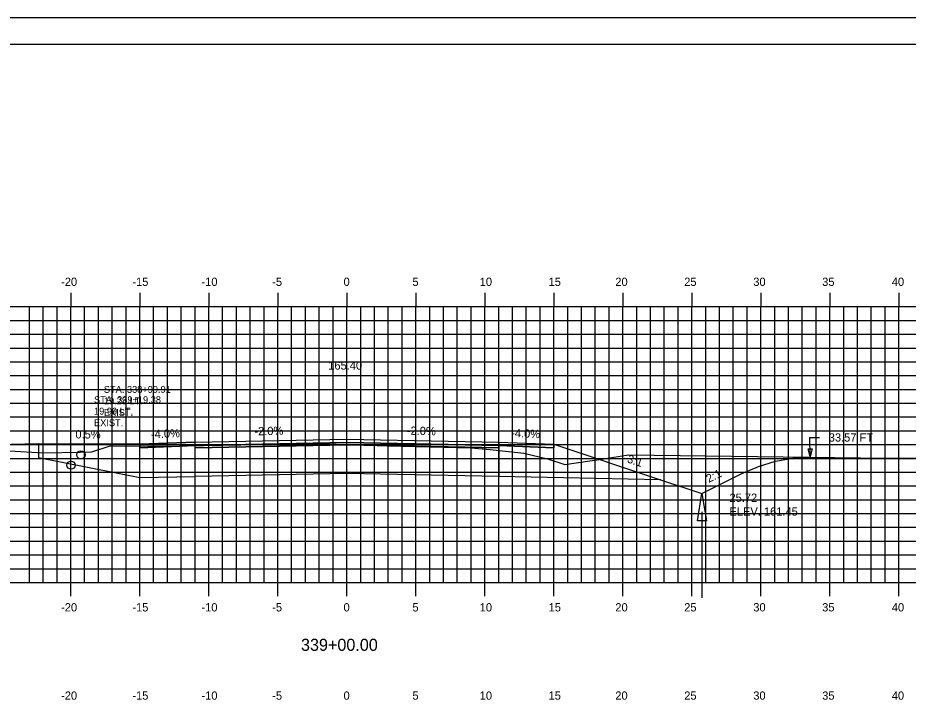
# Model space of a CAD drawing. Extents: x 1142533 to 1142703, y 608981 to 609091.
# Drawn here: x 1142592.2 to 1142656.7, y 609041.6 to 609091.3 of the extents above; entities that cross this region are included whole.
import ezdxf

# ---------------------------------------------------------------- set-up
doc = ezdxf.new("R2010")
doc.units = 0
for name, color, linetype in [('ANNOTATION', 7, 'Continuous'), ('BORDER', 7, 'Continuous'), ('D_Drainage_Ditch_Line', 7, 'Continuous'), ('D_Roadway_Centerline', 7, 'Continuous'), ('D_Roadway_Centerline_Text', 7, 'Continuous'), ('D_Roadway_Edge_Shoulder', 7, 'Continuous'), ('D_Roadway_Edge_TW', 7, 'Continuous'), ('D_Roadway_Pavement', 7, 'Continuous'), ('D_Roadway_SlopeLines', 7, 'Continuous'), ('D_Roadway_SubGrade', 7, 'Continuous'), ('D_Text_Monospaced', 7, 'Continuous'), ('D_Text_Standard', 7, 'Continuous'), ('H_V ANNOTATION', 7, 'Continuous'), ('MAJOR', 7, 'Continuous'), ('MINOR', 7, 'Continuous'), ('PLOT BOUNDARY', 7, 'Continuous'), ('S_Drainage_Invert', 7, 'Continuous'), ('S_Roadway_Centerline', 7, 'Continuous')]:
    doc.layers.add(name, color=color, linetype=linetype)

msp = doc.modelspace()

# ---------------------------------------------------------------- linework, layer by layer
msp.add_lwpolyline([(1142593.711, 609060.391), (1142601.053, 609060.355), (1142605.053, 609060.515), (1142616.053, 609060.735), (1142627.053, 609060.515), (1142631.053, 609060.355), (1142638.777, 609057.78), (1142641.777, 609056.78), (1142644.62, 609058.202), (1142645.87, 609058.747), (1142647.12, 609059.131), (1142648.37, 609059.355), (1142649.62, 609059.418)])
at = {"layer": 'BORDER'}
msp.add_lwpolyline([(1142541.054, 608984.335), (1142701.054, 608984.335), (1142701.054, 609089.335), (1142541.054, 609089.335)], close=True, dxfattribs=at)
at = {"layer": 'D_Drainage_Ditch_Line'}
msp.add_line((1142641.777, 609055.468), (1142641.777, 609049.224), dxfattribs=at)
msp.add_lwpolyline([(1142642.105, 609054.812), (1142641.449, 609054.812), (1142641.777, 609056.78)], close=True, dxfattribs=at)
at = {"layer": 'D_Roadway_Edge_Shoulder'}
for points in [[(1142605.053, 609060.515), (1142601.053, 609060.355), (1142601.053, 609060.105), (1142605.053, 609060.265)], [(1142627.053, 609060.515), (1142631.053, 609060.355), (1142631.053, 609060.105), (1142627.053, 609060.265)]]:
    msp.add_lwpolyline(points, close=True, dxfattribs=at)
at = {"layer": 'D_Roadway_Edge_TW'}
msp.add_lwpolyline([(1142605.053, 609060.265), (1142605.053, 609060.515), (1142616.053, 609060.735), (1142627.053, 609060.515), (1142627.053, 609060.265), (1142616.053, 609060.485)], close=True, dxfattribs=at)
at = {"layer": 'D_Roadway_Pavement'}
msp.add_lwpolyline([(1142605.053, 609060.098), (1142605.053, 609060.265), (1142616.053, 609060.485), (1142627.053, 609060.265), (1142627.053, 609060.098), (1142616.053, 609060.318)], close=True, dxfattribs=at)
at = {"layer": 'D_Roadway_SlopeLines'}
msp.add_line((1142593.711, 609060.391), (1142583.639, 609060.126), dxfattribs=at)
for points in [[(1142641.777, 609056.78), (1142644.62, 609058.202), (1142645.87, 609058.747), (1142647.12, 609059.131), (1142648.37, 609059.355), (1142649.62, 609059.418)], [(1142638.777, 609057.78), (1142641.777, 609056.78)]]:
    msp.add_lwpolyline(points, dxfattribs=at)
at = {"layer": 'D_Roadway_SubGrade'}
for points in [[(1142593.711, 609059.391), (1142601.053, 609057.935), (1142605.053, 609058.015), (1142605.053, 609060.098), (1142605.053, 609060.265), (1142601.053, 609060.105), (1142601.053, 609060.355), (1142593.711, 609060.391)], [(1142605.053, 609058.015), (1142605.053, 609060.098), (1142616.053, 609060.318), (1142627.053, 609060.098), (1142627.053, 609058.015), (1142616.053, 609058.235)], [(1142627.053, 609060.098), (1142627.053, 609060.265), (1142631.053, 609060.105), (1142631.053, 609060.355), (1142631.054, 609060.355), (1142638.777, 609057.78), (1142627.053, 609058.015)]]:
    msp.add_lwpolyline(points, close=True, dxfattribs=at)
at = {"layer": 'D_Text_Standard'}
msp.add_lwpolyline([(1142649.62, 609059.452), (1142649.611, 609060.849), (1142650.291, 609060.849)], dxfattribs=at)
msp.add_lwpolyline([(1142649.62, 609059.452), (1142649.471, 609060.033), (1142649.762, 609060.035)], close=True, dxfattribs=at)
at = {"layer": 'MAJOR'}
for p, q in [((1142596.053, 609071.337), (1142596.053, 609070.335)), ((1142601.053, 609071.337), (1142601.053, 609070.335)), ((1142606.053, 609071.337), (1142606.053, 609070.335)), ((1142611.053, 609071.337), (1142611.053, 609070.335)), ((1142616.053, 609071.337), (1142616.053, 609070.335)), ((1142621.053, 609071.337), (1142621.053, 609070.335)), ((1142626.053, 609071.337), (1142626.053, 609070.335)), ((1142631.053, 609071.337), (1142631.053, 609070.335)), ((1142636.053, 609071.337), (1142636.053, 609070.335)), ((1142641.053, 609071.337), (1142641.053, 609070.335)), ((1142646.053, 609071.337), (1142646.053, 609070.335)), ((1142651.053, 609071.337), (1142651.053, 609070.335)), ((1142656.053, 609071.337), (1142656.053, 609070.335)), ((1142546.053, 609070.335), (1142686.053, 609070.335)), ((1142546.053, 609070.335), (1142686.053, 609070.335)), ((1142596.053, 609050.335), (1142596.053, 609070.335)), ((1142601.053, 609050.335), (1142601.053, 609070.335)), ((1142606.053, 609050.335), (1142606.053, 609070.335)), ((1142611.053, 609050.335), (1142611.053, 609070.335)), ((1142616.053, 609050.335), (1142616.053, 609070.335)), ((1142621.053, 609050.335), (1142621.053, 609070.335)), ((1142626.053, 609050.335), (1142626.053, 609070.335)), ((1142631.053, 609050.335), (1142631.053, 609070.335)), ((1142636.053, 609050.335), (1142636.053, 609070.335)), ((1142641.053, 609050.335), (1142641.053, 609070.335)), ((1142646.053, 609050.335), (1142646.053, 609070.335)), ((1142651.053, 609050.335), (1142651.053, 609070.335)), ((1142656.053, 609050.335), (1142656.053, 609070.335)), ((1142546.053, 609065.335), (1142686.053, 609065.335)), ((1142546.053, 609060.335), (1142686.053, 609060.335)), ((1142546.053, 609055.335), (1142686.053, 609055.335)), ((1142546.053, 609050.335), (1142686.053, 609050.335)), ((1142546.053, 609050.335), (1142686.053, 609050.335)), ((1142596.053, 609049.333), (1142596.053, 609050.335)), ((1142601.053, 609049.333), (1142601.053, 609050.335)), ((1142606.053, 609049.333), (1142606.053, 609050.335)), ((1142611.053, 609049.333), (1142611.053, 609050.335)), ((1142616.053, 609049.333), (1142616.053, 609050.335)), ((1142621.053, 609049.333), (1142621.053, 609050.335)), ((1142626.053, 609049.333), (1142626.053, 609050.335)), ((1142631.053, 609049.333), (1142631.053, 609050.335)), ((1142636.053, 609049.333), (1142636.053, 609050.335)), ((1142641.053, 609049.333), (1142641.053, 609050.335)), ((1142646.053, 609049.333), (1142646.053, 609050.335)), ((1142651.053, 609049.333), (1142651.053, 609050.335)), ((1142656.053, 609049.333), (1142656.053, 609050.335))]:
    msp.add_line(p, q, dxfattribs=at)
at = {"layer": 'MINOR'}
for p, q in [((1142593.053, 609050.335), (1142593.053, 609070.335)), ((1142594.053, 609050.335), (1142594.053, 609070.335)), ((1142595.053, 609050.335), (1142595.053, 609070.335)), ((1142597.053, 609050.335), (1142597.053, 609070.335)), ((1142598.053, 609050.335), (1142598.053, 609070.335)), ((1142599.053, 609050.335), (1142599.053, 609070.335)), ((1142600.053, 609050.335), (1142600.053, 609070.335)), ((1142602.053, 609050.335), (1142602.053, 609070.335)), ((1142603.053, 609050.335), (1142603.053, 609070.335)), ((1142604.053, 609050.335), (1142604.053, 609070.335)), ((1142605.053, 609050.335), (1142605.053, 609070.335)), ((1142607.053, 609050.335), (1142607.053, 609070.335)), ((1142608.053, 609050.335), (1142608.053, 609070.335)), ((1142609.053, 609050.335), (1142609.053, 609070.335)), ((1142610.053, 609050.335), (1142610.053, 609070.335)), ((1142612.053, 609050.335), (1142612.053, 609070.335)), ((1142613.053, 609050.335), (1142613.053, 609070.335)), ((1142614.053, 609050.335), (1142614.053, 609070.335)), ((1142615.053, 609050.335), (1142615.053, 609070.335)), ((1142617.053, 609050.335), (1142617.053, 609070.335)), ((1142618.053, 609050.335), (1142618.053, 609070.335)), ((1142619.053, 609050.335), (1142619.053, 609070.335)), ((1142620.053, 609050.335), (1142620.053, 609070.335)), ((1142622.053, 609050.335), (1142622.053, 609070.335)), ((1142623.053, 609050.335), (1142623.053, 609070.335)), ((1142624.053, 609050.335), (1142624.053, 609070.335)), ((1142625.053, 609050.335), (1142625.053, 609070.335)), ((1142627.053, 609050.335), (1142627.053, 609070.335)), ((1142628.053, 609050.335), (1142628.053, 609070.335)), ((1142629.053, 609050.335), (1142629.053, 609070.335)), ((1142630.053, 609050.335), (1142630.053, 609070.335)), ((1142632.053, 609050.335), (1142632.053, 609070.335)), ((1142633.053, 609050.335), (1142633.053, 609070.335)), ((1142634.053, 609050.335), (1142634.053, 609070.335)), ((1142635.053, 609050.335), (1142635.053, 609070.335)), ((1142637.053, 609050.335), (1142637.053, 609070.335)), ((1142638.053, 609050.335), (1142638.053, 609070.335)), ((1142639.053, 609050.335), (1142639.053, 609070.335)), ((1142640.053, 609050.335), (1142640.053, 609070.335)), ((1142642.053, 609050.335), (1142642.053, 609070.335)), ((1142643.053, 609050.335), (1142643.053, 609070.335)), ((1142644.053, 609050.335), (1142644.053, 609070.335)), ((1142645.053, 609050.335), (1142645.053, 609070.335)), ((1142647.053, 609050.335), (1142647.053, 609070.335)), ((1142648.053, 609050.335), (1142648.053, 609070.335)), ((1142649.053, 609050.335), (1142649.053, 609070.335)), ((1142650.053, 609050.335), (1142650.053, 609070.335)), ((1142652.053, 609050.335), (1142652.053, 609070.335)), ((1142653.053, 609050.335), (1142653.053, 609070.335)), ((1142654.053, 609050.335), (1142654.053, 609070.335)), ((1142655.053, 609050.335), (1142655.053, 609070.335)), ((1142546.053, 609069.335), (1142686.053, 609069.335)), ((1142546.053, 609068.335), (1142686.053, 609068.335)), ((1142546.053, 609067.335), (1142686.053, 609067.335)), ((1142546.053, 609066.335), (1142686.053, 609066.335)), ((1142546.053, 609064.335), (1142686.053, 609064.335)), ((1142546.053, 609063.335), (1142686.053, 609063.335)), ((1142546.053, 609062.335), (1142686.053, 609062.335)), ((1142546.053, 609061.335), (1142686.053, 609061.335)), ((1142546.053, 609059.335), (1142686.053, 609059.335)), ((1142546.053, 609058.335), (1142686.053, 609058.335)), ((1142546.053, 609057.335), (1142686.053, 609057.335)), ((1142546.053, 609056.335), (1142686.053, 609056.335)), ((1142546.053, 609054.335), (1142686.053, 609054.335)), ((1142546.053, 609053.335), (1142686.053, 609053.335)), ((1142546.053, 609052.335), (1142686.053, 609052.335)), ((1142546.053, 609051.335), (1142686.053, 609051.335))]:
    msp.add_line(p, q, dxfattribs=at)
at = {"layer": 'PLOT BOUNDARY'}
msp.add_lwpolyline([(1142532.96, 608981.276), (1142702.96, 608981.276), (1142702.96, 609091.276), (1142532.96, 609091.276)], close=True, dxfattribs=at)
at = {"layer": 'S_Drainage_Invert'}
for centre in [(1142596.778, 609059.586), (1142596.065, 609058.84)]:
    msp.add_circle(centre, 0.3, dxfattribs=at)
at = {"layer": 'S_Roadway_Centerline'}
msp.add_lwpolyline([(1142546.053, 609060.596), (1142564.136, 609060.407), (1142571.113, 609060.438), (1142586.023, 609060.066), (1142589.149, 609060.035), (1142594.057, 609059.733), (1142596.736, 609059.787), (1142597.575, 609059.795), (1142598.896, 609060.234), (1142602.888, 609060.217), (1142602.895, 609060.218), (1142602.929, 609060.219), (1142613.821, 609060.416), (1142618.977, 609060.242), (1142625.024, 609060.106), (1142626.441, 609059.985), (1142628.873, 609059.705), (1142630.597, 609059.311), (1142631.85, 609058.883), (1142634.658, 609059.303), (1142636.46, 609059.594), (1142653.28, 609059.37), (1142667.439, 609059.325), (1142686.053, 609059.248)], dxfattribs=at)

# ---------------------------------------------------------------- texts
at = {"layer": 'ANNOTATION'}
for s, rotation, p in [('0.5%', 359.71352, (1142596.381, 609060.778)), ('-4.0%', 2.29061, (1142601.869, 609060.788)), ('-2.0%', 1.14576, (1142609.356, 609061.001)), ('-2.0%', 358.85424, (1142620.396, 609061.048)), ('-4.0%', 357.70939, (1142627.949, 609060.88)), ('-3:1', 341.56521, (1142636.065, 609059.138)), ('2:1', 26.56505, (1142642.271, 609057.545))]:
    msp.add_text(s, height=0.6, rotation=rotation, dxfattribs=at).set_placement(p)
at = {"layer": 'D_Roadway_Centerline'}
for s, p in [('C', (1142616.048, 609060.735)), ('L', (1142616.053, 609060.727))]:
    msp.add_text(s, height=0.0146, dxfattribs=at).set_placement(p)
at = {"layer": 'D_Roadway_Centerline_Text'}
msp.add_text('165.40', height=0.6, dxfattribs=at).set_placement((1142614.705, 609065.767))
at = {"layer": 'D_Text_Monospaced'}
for s, height, p in [('STA. 338+99.91', 0.49998, (1142598.445, 609064.084)), ('STA. 339+19.38', 0.49998, (1142597.732, 609063.338)), ('19.28 LT.', 0.5, (1142598.445, 609063.25)), ('19.99 LT.', 0.5, (1142597.732, 609062.504)), ('EXIST. ', 0.5, (1142598.445, 609062.41)), ('EXIST. ', 0.5, (1142597.732, 609061.664))]:
    msp.add_text(s, height=height, dxfattribs=at).set_placement(p)
at = {"layer": 'D_Text_Standard'}
for s, p in [('33.57 FT', (1142650.971, 609060.549)), ('25.72', (1142643.777, 609056.18)), ('ELEV. 161.45', (1142643.777, 609055.178))]:
    msp.add_text(s, height=0.6, dxfattribs=at).set_placement(p)
at = {"layer": 'H_V ANNOTATION'}
for s, height, p in [('-20', 0.6, (1142595.347, 609071.835)), ('-15', 0.6, (1142600.51, 609071.835)), ('-10', 0.6, (1142605.518, 609071.835)), ('-5', 0.6, (1142610.644, 609071.835)), ('0', 0.6, (1142615.813, 609071.835)), ('5', 0.6, (1142620.804, 609071.835)), ('10', 0.6, (1142625.679, 609071.835)), ('15', 0.6, (1142630.671, 609071.835)), ('20', 0.6, (1142635.507, 609071.835)), ('25', 0.6, (1142640.499, 609071.835)), ('30', 0.6, (1142645.502, 609071.835)), ('35', 0.6, (1142650.494, 609071.835)), ('40', 0.6, (1142655.54, 609071.835)), ('-20', 0.6, (1142595.347, 609048.235)), ('-15', 0.6, (1142600.51, 609048.235)), ('-10', 0.6, (1142605.518, 609048.235)), ('-5', 0.6, (1142610.644, 609048.235)), ('0', 0.6, (1142615.813, 609048.235)), ('5', 0.6, (1142620.804, 609048.235)), ('10', 0.6, (1142625.679, 609048.235)), ('15', 0.6, (1142630.671, 609048.235)), ('20', 0.6, (1142635.507, 609048.235)), ('25', 0.6, (1142640.499, 609048.235)), ('30', 0.6, (1142645.502, 609048.235)), ('35', 0.6, (1142650.494, 609048.235)), ('40', 0.6, (1142655.54, 609048.235)), ('339+00.00', 0.875, (1142612.729, 609045.378)), ('-20', 0.6, (1142595.347, 609041.835)), ('-15', 0.6, (1142600.51, 609041.835)), ('-10', 0.6, (1142605.518, 609041.835)), ('-5', 0.6, (1142610.644, 609041.835)), ('0', 0.6, (1142615.813, 609041.835)), ('5', 0.6, (1142620.804, 609041.835)), ('10', 0.6, (1142625.679, 609041.835)), ('15', 0.6, (1142630.671, 609041.835)), ('20', 0.6, (1142635.507, 609041.835)), ('25', 0.6, (1142640.499, 609041.835)), ('30', 0.6, (1142645.502, 609041.835)), ('35', 0.6, (1142650.494, 609041.835)), ('40', 0.6, (1142655.54, 609041.835))]:
    msp.add_text(s, height=height, dxfattribs=at).set_placement(p)
at = {"layer": 'S_Roadway_Centerline'}
for s, p in [('L', (1142613.813, 609060.409)), ('C', (1142613.816, 609060.416))]:
    msp.add_text(s, height=0.0146, dxfattribs=at).set_placement(p)

doc.saveas('drawing.dxf')
